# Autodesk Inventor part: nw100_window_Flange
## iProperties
Shininess: 64.0
Length Units: 11269
Angle Units: 11279
Time Units: 11290
Mass Units: 11283
Length Display Precision: 3
Angle Display Precision: 2
Compacted: True
Part Number: nw100_window_Flange
Document SubType Name: Modeling
Created: 2003-05
Designer: John Blackburn
Density: 0.0
Volumn: 0.0
Area: 0.0
PropertySet Name: Model Information
Control State: 0
Master: False
Checked Out: False
Author: John Blackburn
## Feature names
1. Revolution1
2. Chamfer1
3. Hole1
4. Circular Pattern2
